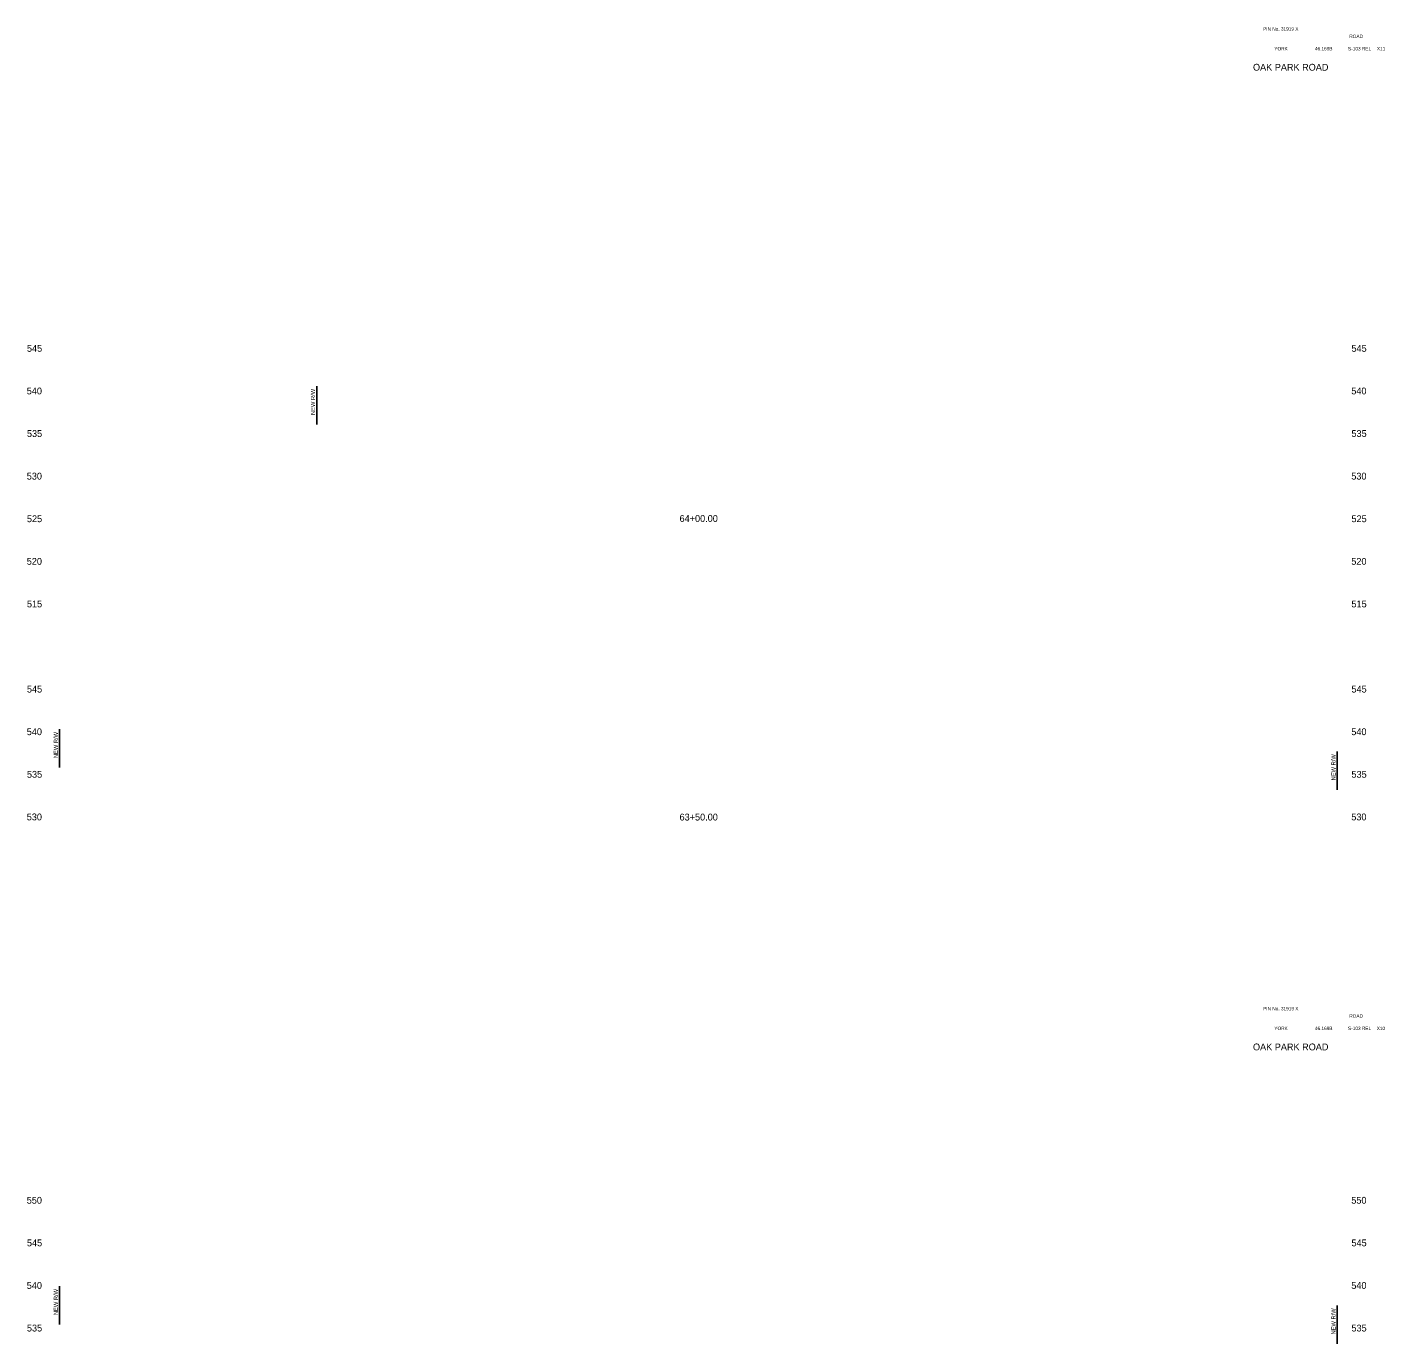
# Model space of a CAD drawing. Extents: x 1001 to 1161, y 1005 to 3518.
# Drawn here: x 1001.2 to 1160.6, y 2098.6 to 2253.2 of the extents above; entities that cross this region are included whole.
import ezdxf

# ---------------------------------------------------------------- set-up
doc = ezdxf.new("R2010")
doc.units = 0
for name, color, linetype in [('RD_SHT_TX', 7, 'Continuous'), ('RD_XS_NewRW', 7, 'Continuous'), ('RD_XS_TX_Elev_EX', 7, 'Continuous'), ('RD_XS_TX_Station', 7, 'Continuous')]:
    doc.layers.add(name, color=color, linetype=linetype)

msp = doc.modelspace()

# ---------------------------------------------------------------- linework, layer by layer
at = {"layer": 'RD_XS_NewRW'}
for p, q in [((1035.18, 2211.08), (1035.18, 2206.58)), ((1005, 2170.8), (1005, 2166.3)), ((1155, 2168.18), (1155, 2163.68)), ((1005, 2105.42), (1005, 2100.92)), ((1155, 2103.15), (1155, 2098.65))]:
    msp.add_line(p, q, dxfattribs=at)

# ---------------------------------------------------------------- texts
at = {"layer": 'RD_SHT_TX'}
for s, height, p in [('PIN No. 31919 X', 0.4, (1146.29, 2252.8)), ('ROAD', 0.4, (1156.41, 2251.93)), ('YORK', 0.4, (1147.61, 2250.48)), ('46.169B', 0.4, (1152.37, 2250.48)), ('S-103 REL', 0.4, (1156.26, 2250.48)), ('X11', 0.4, (1159.65, 2250.48)), ('OAK PARK ROAD', 0.8, (1145.1, 2248.1)), ('PIN No. 31919 X', 0.4, (1146.29, 2137.8)), ('YORK', 0.4, (1147.61, 2135.48)), ('46.169B', 0.4, (1152.37, 2135.48)), ('S-103 REL', 0.4, (1156.26, 2135.48)), ('ROAD', 0.4, (1156.41, 2136.93)), ('X10', 0.4, (1159.63, 2135.48)), ('OAK PARK ROAD', 0.8, (1145.1, 2133.1))]:
    msp.add_text(s, height=height, dxfattribs=at).set_placement(p)
at = {"layer": 'RD_XS_NewRW'}
for p in [(1034.98, 2207.68), (1004.8, 2167.4), (1154.8, 2164.79), (1004.8, 2102.02), (1154.8, 2099.75)]:
    msp.add_text('NEW R/W ', height=0.488, rotation=90, dxfattribs=at).set_placement(p)
at = {"layer": 'RD_XS_TX_Elev_EX'}
for s, p in [('545', (1001.16, 2215.1)), ('545', (1156.66, 2215.1)), ('540', (1001.14, 2210.1)), ('540', (1156.64, 2210.1)), ('535', (1001.16, 2205.1)), ('535', (1156.66, 2205.1)), ('530', (1001.14, 2200.1)), ('530', (1156.64, 2200.1)), ('525', (1001.16, 2195.1)), ('525', (1156.66, 2195.1)), ('520', (1001.14, 2190.1)), ('520', (1156.64, 2190.1)), ('515', (1001.16, 2185.1)), ('515', (1156.66, 2185.1)), ('545', (1001.16, 2175.1)), ('545', (1156.66, 2175.1)), ('540', (1001.14, 2170.1)), ('540', (1156.64, 2170.1)), ('535', (1001.16, 2165.1)), ('535', (1156.66, 2165.1)), ('530', (1001.14, 2160.1)), ('530', (1156.64, 2160.1)), ('550', (1001.14, 2115.1)), ('550', (1156.64, 2115.1)), ('545', (1001.16, 2110.1)), ('545', (1156.66, 2110.1)), ('540', (1001.14, 2105.1)), ('540', (1156.64, 2105.1)), ('535', (1001.16, 2100.1)), ('535', (1156.66, 2100.1))]:
    msp.add_text(s, height=0.8, dxfattribs=at).set_placement(p)
at = {"layer": 'RD_XS_TX_Station'}
for s, p in [('64+00.00', (1077.78, 2195.13)), ('63+50.00', (1077.78, 2160.08))]:
    msp.add_text(s, height=0.8, dxfattribs=at).set_placement(p)

doc.saveas('drawing.dxf')
